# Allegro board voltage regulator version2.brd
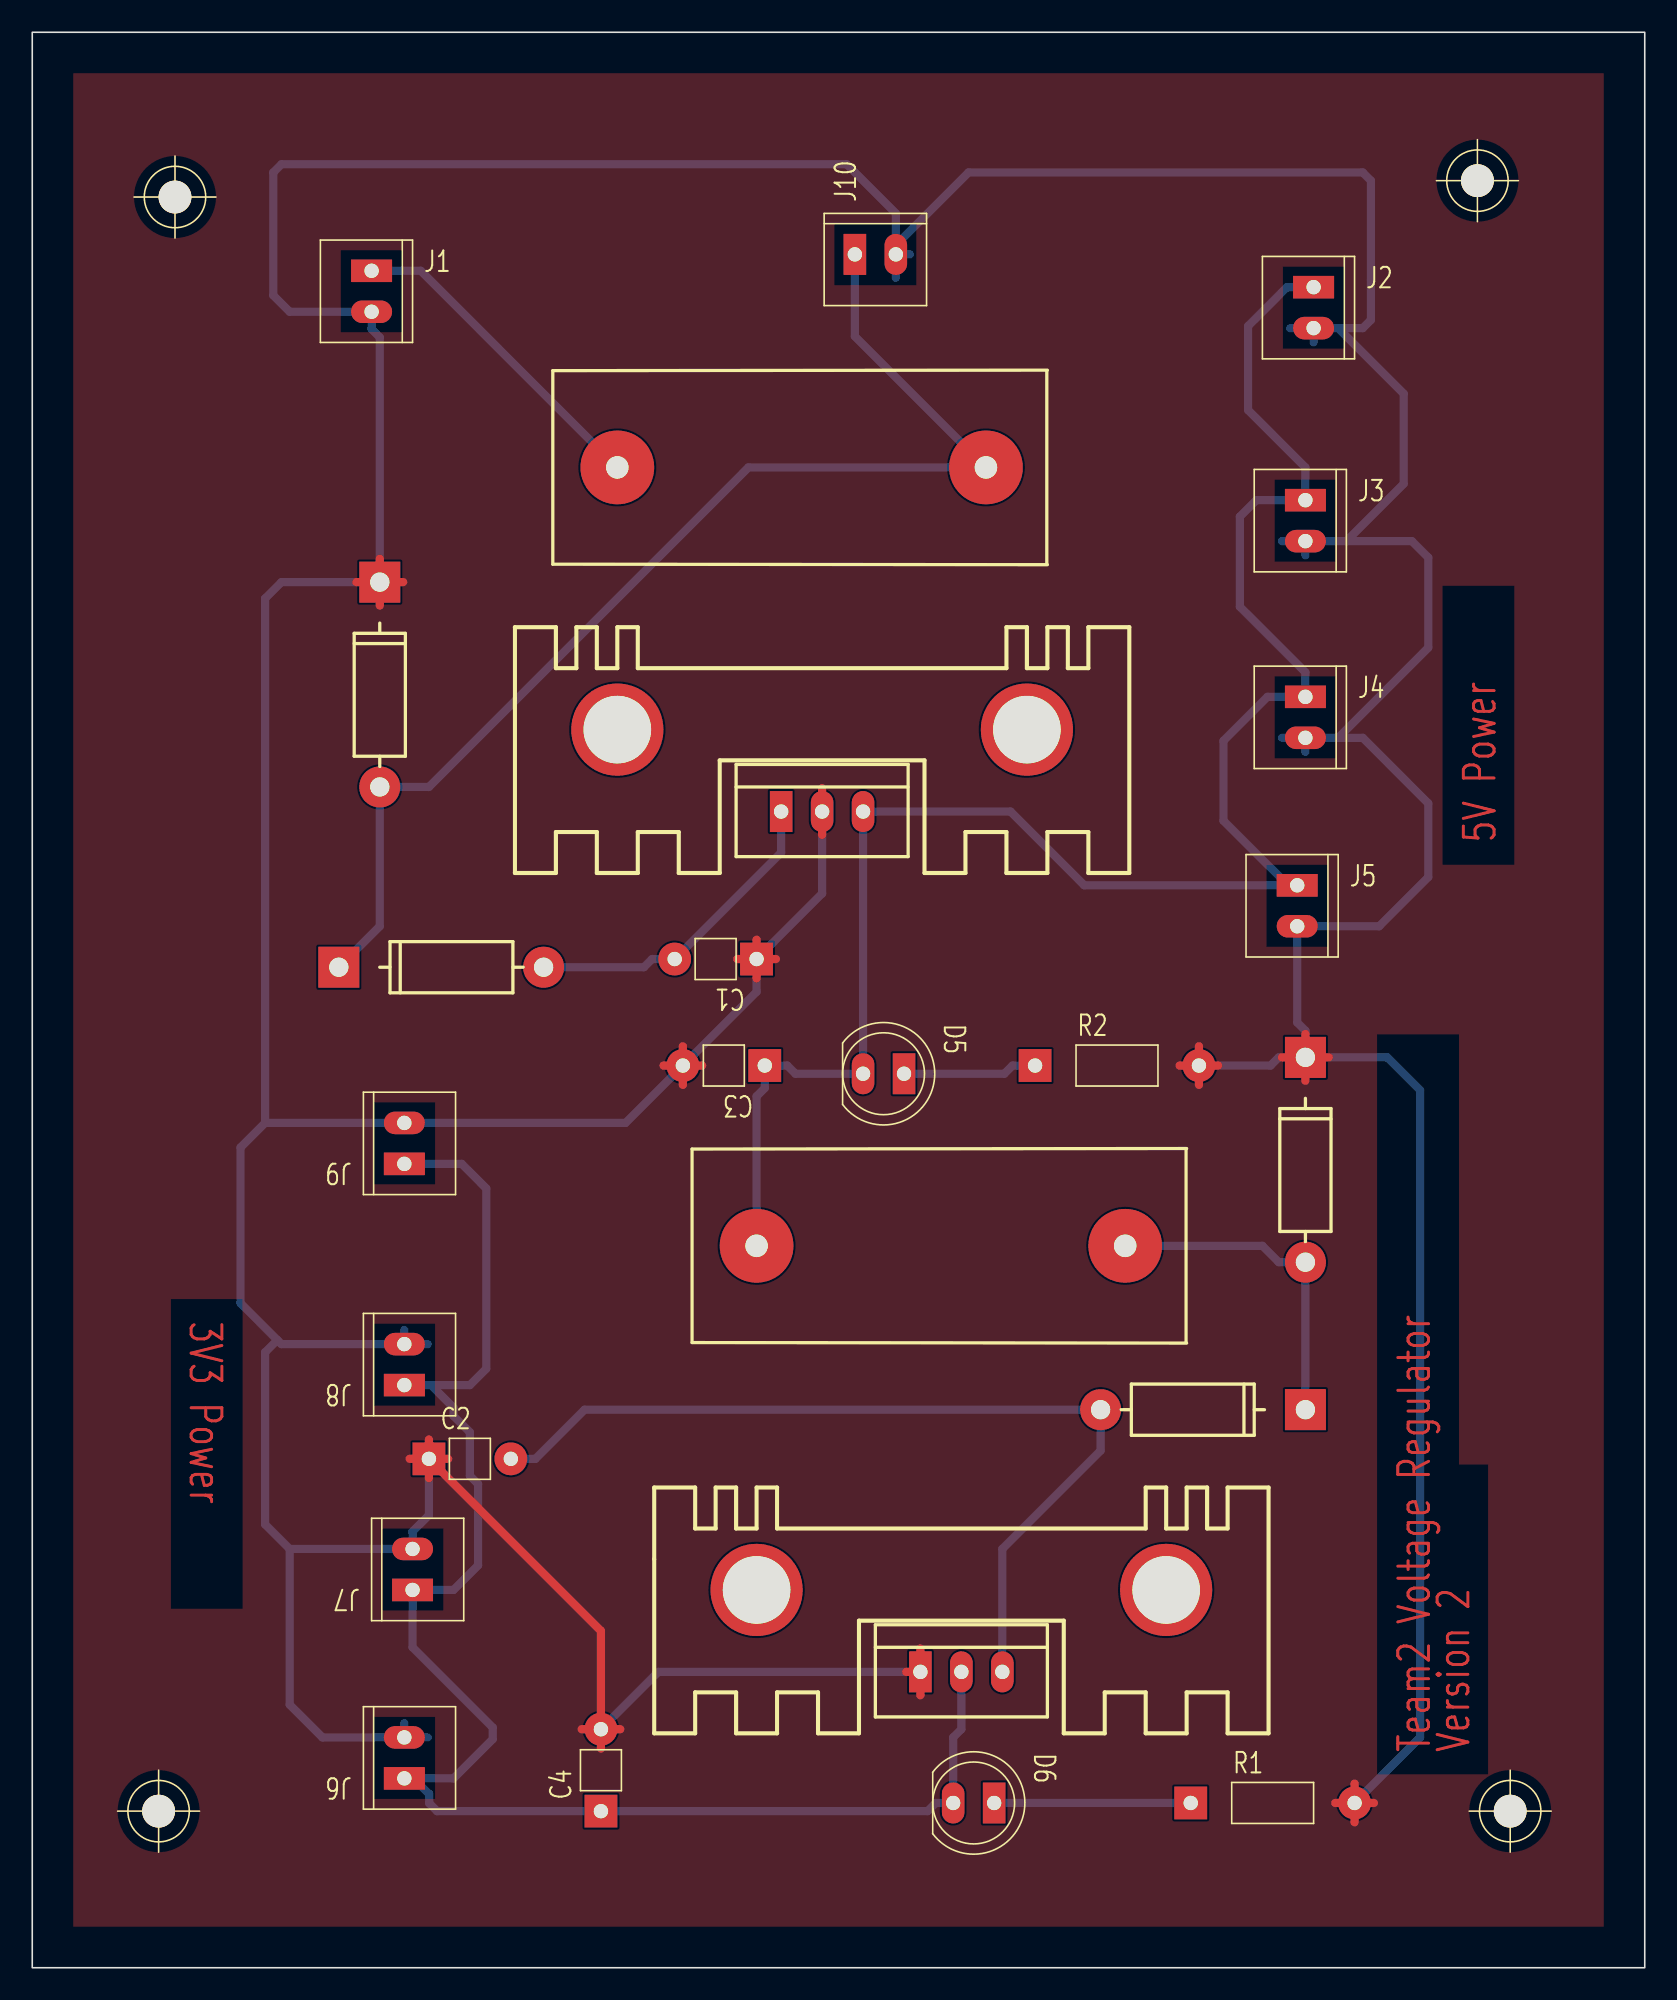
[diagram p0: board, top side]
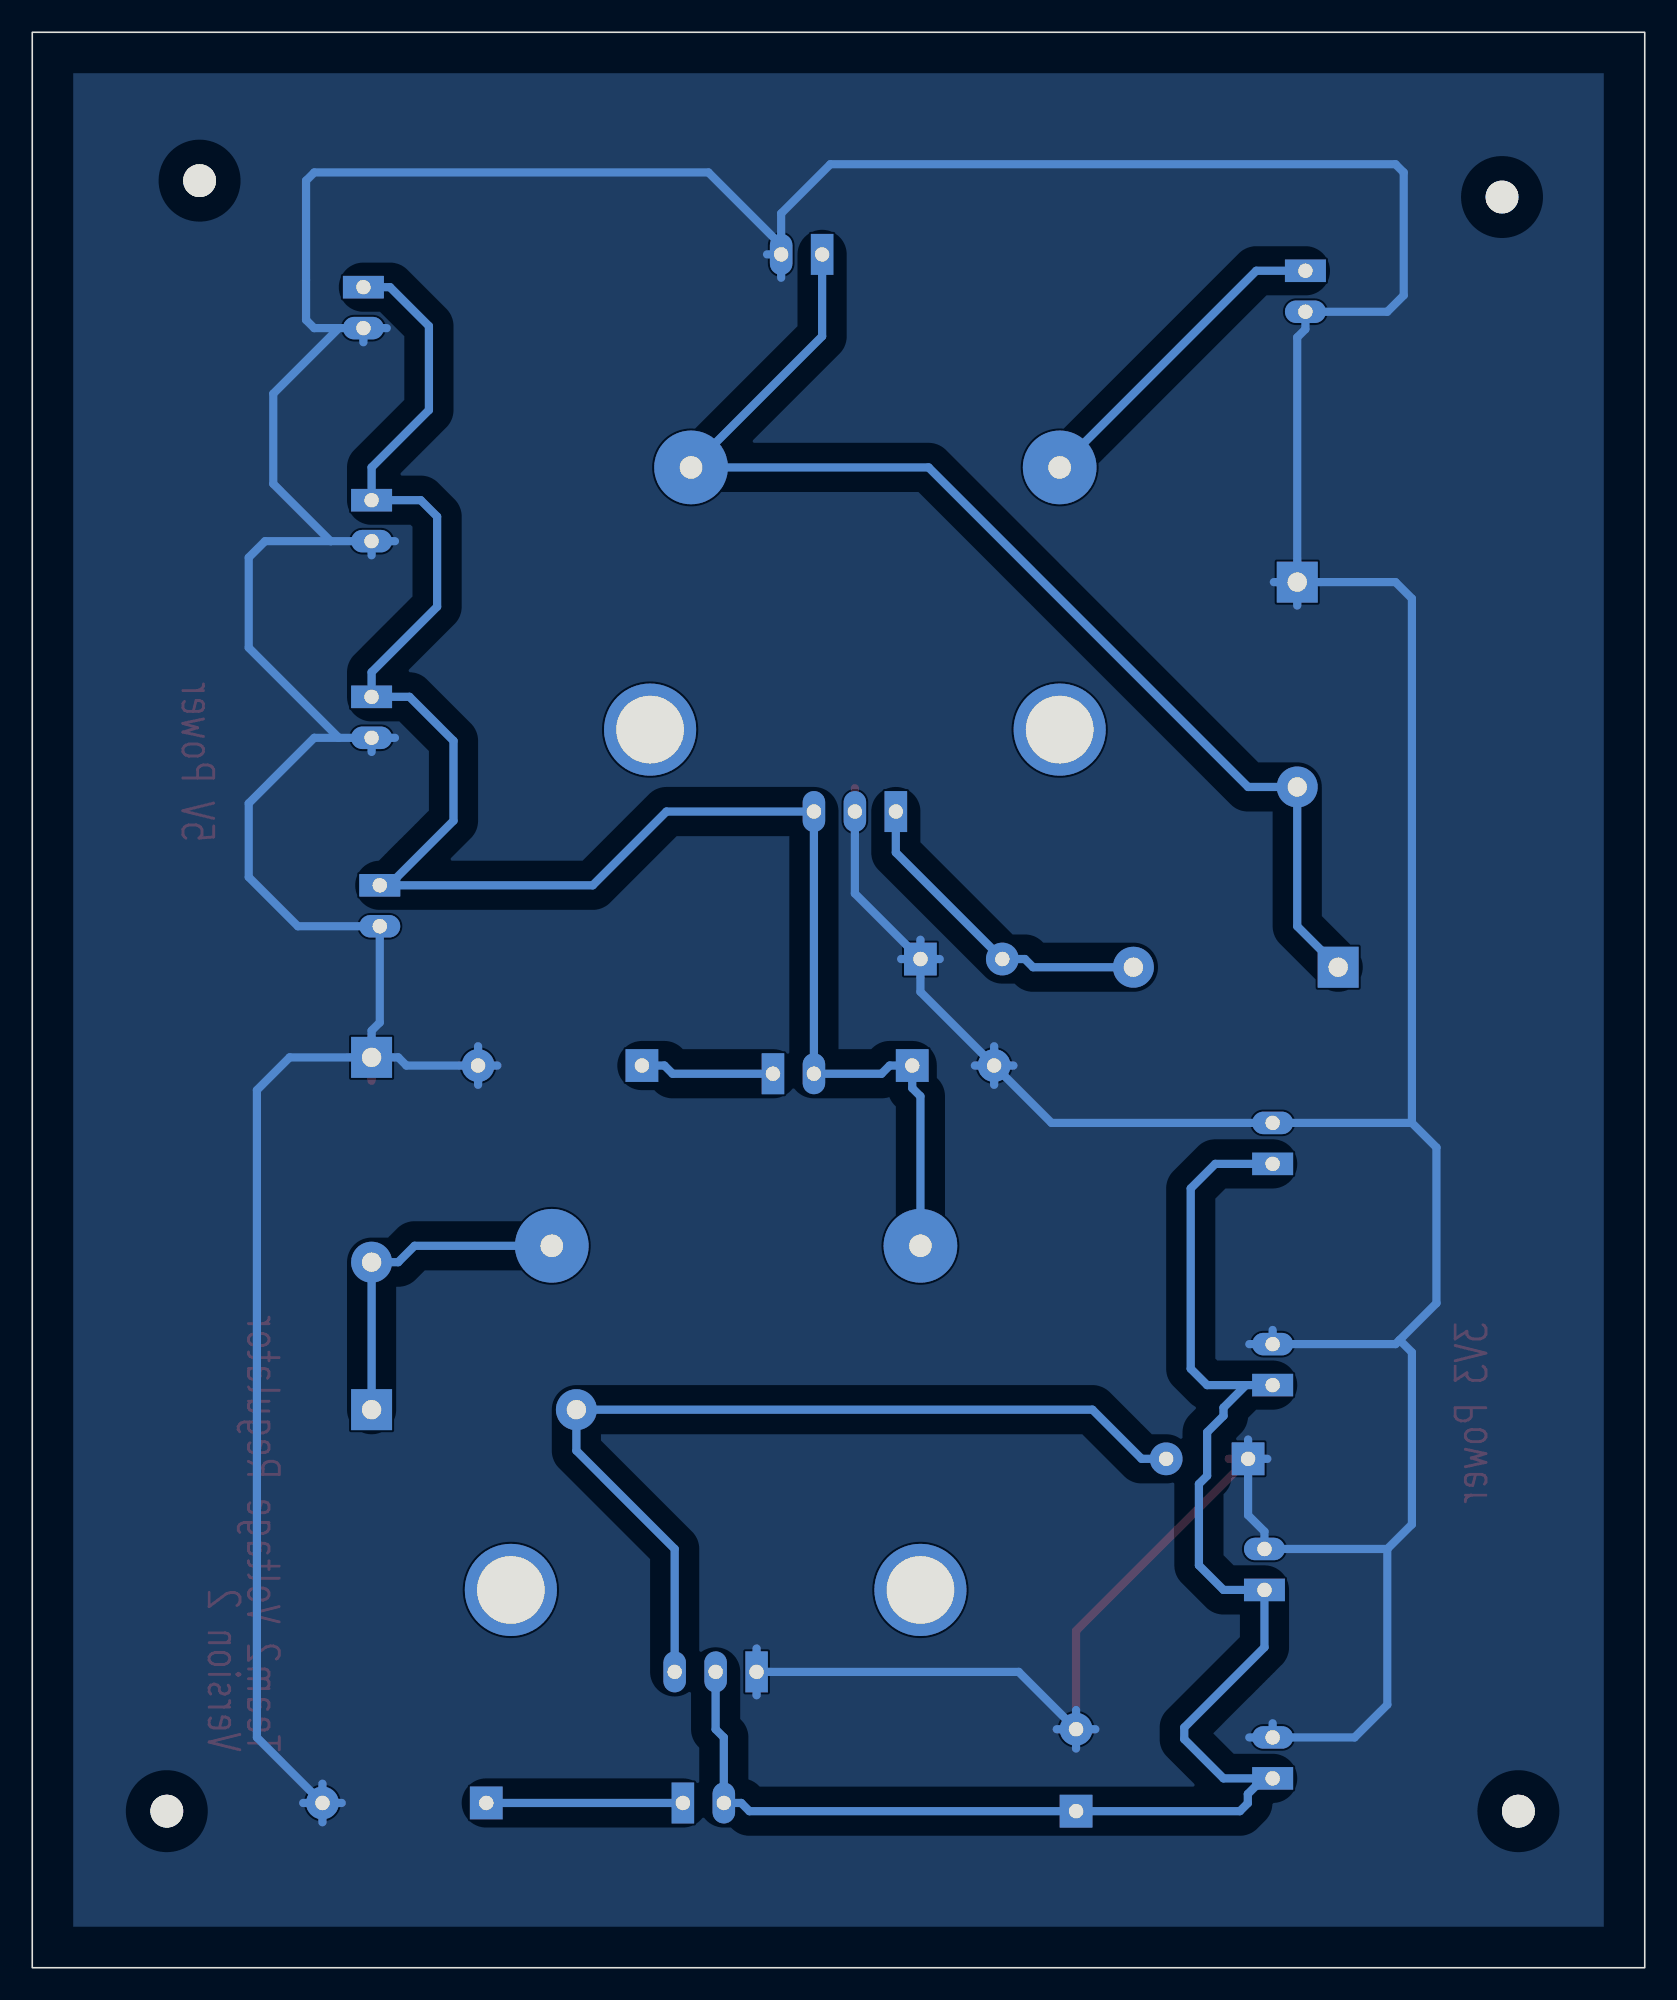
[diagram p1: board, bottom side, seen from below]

Outline 100 x 120 mm; copper layers: TOP, BOTTOM. Coordinates in mm from the lower left corner of the outline.
Outline path: rectangle 0,0 100,120

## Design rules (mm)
constraint set DEFAULT: min track width 0.508

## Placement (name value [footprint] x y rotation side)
C1  470n  [GU-RC200]  44.92 62.54 180 top
C2  100n  [GU-RC200]  24.6 31.55 0 top
C3  220n  [GU-RC200]  45.43 55.94 180 top
C4  10u  [GU-RC200]  35.27 9.71 90 top
D1  DIODE ZENER  [GU-1N4001]  78.96 56.44 270 top
D2  DIODE ZENER  [GU-1N4001]  21.55 85.91 270 top
D5  LED  [GU-LED5MM]  54.06 55.43 270 top
D6  LED  [GU-LED5MM]  59.65 10.22 270 top
D7  DIODE  [GU-1N4001]  19.01 62.03 0 top
D8  DIODE  [GU-1N4001]  78.96 34.6 180 top
F1  FUSEHOLDER  [GU-FUSEHOLDER-20MM]  36.28 93.02 0 top
F2  FUSEHOLDER  [GU-FUSEHOLDER-20MM]  44.92 44.76 0 top
J1  Battery Input  [GU-MOLEX2]  21.04 105.21 0 top
J2  5V Supply  [GU-MOLEX2]  79.46 104.2 0 top
J3  5V Supply  [GU-MOLEX2]  78.96 90.99 0 top
J4  5V Supply  [GU-MOLEX2]  78.96 78.8 0 top
J5  5V Supply  [GU-MOLEX2]  78.45 67.11 0 top
J6  3V3 Supply  [GU-MOLEX2]  23.08 11.74 180 top
J7  3V3 Supply  [GU-MOLEX2]  23.58 23.42 180 top
J8  3V3 Supply  [GU-MOLEX2]  23.08 36.12 180 top
J9  3V3 Supply  [GU-MOLEX2]  23.08 49.84 180 top
J10  12V Supply  [GU-MOLEX2]  51.02 106.23 90 top
NOREF  -  [unnamed]  8.85 109.78 0 top
NOREF#2  -  [unnamed]  91.66 9.71 0 top
NOREF#3  -  [unnamed]  89.62 110.8 0 top
NOREF#4  -  [unnamed]  7.84 9.71 0 top
R1  430  [GU-RC400]  71.84 10.22 0 top
R2  430  [GU-RC400]  62.19 55.94 0 top
U1  L7805/TO220  [GU-TO220AB-HSINK]  46.44 71.68 0 top
U2  LD1117/DD  [GU-TO220AB-HSINK]  55.08 18.34 0 top

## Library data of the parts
C1-C4 = CAP NP
D1 D2 = DIODE ZENER
D5 D6 = LED
D7 D8 = DIODE
F1 F2 = FUSEHOLDER
J1-J10 = CON2
R1 R2 = R
U1 = L7805/TO220_0
U2 = LD1117/DD_0

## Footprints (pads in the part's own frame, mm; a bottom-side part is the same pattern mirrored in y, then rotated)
GU-1N4001
  round 2.54 hole 1.194: 1(12.7,0)
  rect 2.54x2.54 hole 1.194: 2(0,0)
GU-FUSEHOLDER-20MM
  round 4.572 hole 1.397: 1(0,0) 2(22.86,0)
GU-LED5MM
  rect 2.54x1.397 hole 0.889: 1(0,0)
  oval 2.54x1.397 hole 0.889: 2(0,-2.54)
GU-MOLEX2
  rect 2.54x1.397 hole 0.889: 1(0,0)
  oval 2.54x1.397 hole 0.889: 2(0,-2.54)
GU-RC200
  rect 2.032x2.032 hole 0.889: 1(0,0)
  round 2.032 hole 0.889: 2(5.08,0)
GU-RC400
  rect 2.032x2.032 hole 0.889: 1(0,0)
  round 2.032 hole 0.889: 2(10.16,0)
GU-TO220AB-HSINK
  round 5.715 hole 4.191 unplated: (-10.16,5.08) (15.24,5.08)
  rect 1.397x2.54 hole 0.889: 1(0,0)
  oval 1.397x2.54 hole 0.889: 2(2.54,0) 3(5.08,0)
unnamed
  round 2.032 hole 3.962 unplated: (0,0)

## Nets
3.3V: C4.1 D6.2 J6.1 J7.1 J8.1 J9.1 U2.2(VOUT)
5V: C3.1 D5.2 F2.1 J2.1 J3.1 J4.1 J5.1 U1.3(VOUT)
12V: D2.1(CATHODE) D7.2 F1.2 J10.1
GND: C1.1 C2.1 C3.2 C4.2 D1.2 D2.2 J1.2 J2.2 J3.2 J4.2 J5.2 J6.2 J7.2 J8.2 J9.2 J10.2 R1.2 R2.2 U1.2 U2.1
N00466: D5.1(CATHODE) R2.1
N00539: F1.1 J1.1
N00628: D1.1(CATHODE) D8.2 F2.2
N00681: D6.1(CATHODE) R1.1
N03779: C1.2 D7.1(K) U1.1
N03792: C2.2 D8.1(K) U2.3

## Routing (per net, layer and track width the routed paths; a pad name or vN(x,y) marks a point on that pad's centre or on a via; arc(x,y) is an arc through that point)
3.3V: length 100.5
  BOTTOM w0.508: 23.65,11.74 24.62,10.77 24.62,10.2 25.11,9.71 C4.1 55.52,9.71 56.03,10.22 D6.2 57.11,14.28 57.62,14.79 U2.2 ; 23.65,11.74 J6.1 ; 23.65,11.74 26.12,11.74 28.56,14.17 28.56,14.89 23.58,19.87 J7.1 26.12,23.42 27.65,24.95 27.65,29.99 27.14,30.5 27.14,33.2 26.12,34.22 26.12,34.73 24.73,36.12 ; J9.1 26.63,49.84 28.16,48.32 28.16,37.14 27.14,36.12 24.73,36.12 ; 24.73,36.12 J8.1
5V: length 114.3
  BOTTOM w0.508: J5.1 77.88,67.11 ; 77.88,67.11 73.88,71.11 73.88,76.07 76.6,78.8 J4.1 78.96,80.32 74.89,84.38 74.89,89.97 75.91,90.99 J3.1 78.96,93.02 75.4,96.58 75.4,101.78 77.81,104.2 J2.1 ; 77.88,67.11 65.24,67.11 60.67,71.68 U1.3 D5.2 47.33,55.43 46.82,55.94 C3.1 45.43,54.54 44.92,54.03 F2.1
12V: length 74.6
  BOTTOM w0.508: J10.1 51.02,101.15 F1.2 44.41,93.02 24.6,73.21 D2.1 21.55,64.57 D7.2
GND: length 534.6
  TOP w0.508: 72.35,54.74 R2.2 ; R2.2 73.55,55.94 ; R2.2 71.16,55.94 ; R2.2 72.35,57.13 ; 80.81,10.22 R1.2 ; R1.2 82,9.02 ; R1.2 83.2,10.22 ; R1.2 82,11.41 ; 21.55,84.46 D2.2 ; D2.2 21.55,87.36 ; D2.2 23,85.91 ; D2.2 20.1,85.91 ; 34.07,14.79 C4.2 ; C4.2 36.46,14.79 ; C4.2 35.27,20.88 C2.1 ; C4.2 35.27,13.59 ; 55.08,16.9 U2.1 ; U2.1 54.2,18.34 ; U2.1 55.08,19.79 ; C2.1 24.6,32.75 ; C2.1 25.79,31.55 ; C2.1 23.41,31.55 ; C2.1 24.6,30.36 ; 44.92,61.35 C1.1 ; C1.1 43.73,62.54 ; C1.1 44.92,63.73 ; C1.1 46.11,62.54 ; 40.35,54.74 C3.2 ; C3.2 39.15,55.94 ; C3.2 41.54,55.94 ; C3.2 40.35,57.13 ; 48.98,73.13 U1.2 48.98,70.24 ; D1.2 80.4,56.44 ; D1.2 78.96,57.89 ; D1.2 77.51,56.44 ; D1.2 78.96,55
  BOTTOM w0.508: 15.96,25.96 15.96,16.31 18,14.28 J6.2 ; 15.96,25.96 14.44,27.49 14.44,38.16 15.2,38.92 ; 15.96,25.96 J7.2 23.58,27.04 24.6,28.06 C2.1 ; C1.1 46.11,62.54 ; C1.1 48.98,66.6 U1.2 ; C1.1 44.92,63.73 ; C1.1 43.73,62.54 ; C1.1 44.92,60.51 C3.2 ; J8.2 23.08,39.54 ; J8.2 15.46,38.66 15.2,38.92 ; J8.2 24.52,38.66 ; 81.5,88.45 85.56,88.45 86.58,87.43 86.58,81.84 80.99,76.26 ; 81.5,88.45 J3.2 ; 81.5,88.45 85.05,92 85.05,97.59 80.99,101.66 ; 82,9.02 R1.2 ; R1.2 80.81,10.22 ; R1.2 82,11.41 ; R1.2 86.07,14.28 86.07,54.41 84.04,56.44 D1.2 ; R1.2 83.2,10.22 ; C3.2 40.35,57.13 ; C3.2 36.79,52.38 J9.2 14.44,52.38 ; C3.2 40.35,54.74 ; C3.2 39.15,55.94 ; C3.2 41.54,55.94 ; 14.44,52.38 14.44,84.89 15.46,85.91 D2.2 ; 14.44,52.38 12.92,50.86 12.92,41.2 15.2,38.92 ; C4.2 38.82,18.34 U2.1 ; C4.2 35.27,13.59 ; C4.2 36.46,14.79 ; C4.2 35.27,15.98 ; C4.2 34.07,14.79 ; 79.46,100.78 J2.2 ; J2.2 78.02,101.66 ; J2.2 80.99,101.66 ; 80.99,76.26 82.51,76.26 86.58,72.19 86.58,67.62 83.53,64.57 J5.2 78.45,58.6 78.96,58.09 D1.2 ; 80.99,76.26 J4.2 ; 77.51,88.45 J3.2 ; J3.2 78.96,87.57 ; J10.2 54.43,106.23 ; J10.2 53.56,106.8 ; J10.2 53.56,104.78 ; C2.1 23.41,31.55 ; C2.1 24.6,32.75 ; J6.2 23.08,15.16 ; J6.2 24.52,14.28 ; R2.2 76.8,55.94 77.3,56.44 D1.2 ; R2.2 72.35,57.13 ; R2.2 72.35,54.74 ; R2.2 71.16,55.94 ; 53.56,106.8 53.56,108.77 50.51,111.82 15.46,111.82 14.95,111.31 14.95,103.69 15.96,102.67 J1.2 21.04,101.59 21.55,101.08 D2.2 ; 53.56,106.8 58.06,111.31 82.51,111.31 83.02,110.8 83.02,102.16 82.51,101.66 80.99,101.66 ; 21.55,84.46 D2.2 ; D2.2 23,85.91 ; 77.51,76.26 J4.2 ; J4.2 78.96,75.38 ; U2.1 55.08,19.79 ; U2.1 55.08,16.9
N00466: length 8.3
  BOTTOM w0.508: D5.1 60.29,55.43 60.79,55.94 R2.1
N00539: length 20.3
  BOTTOM w0.508: F1.1 24.09,105.21 J1.1
N00628: length 20.7
  BOTTOM w0.508: D8.2 D1.1 77.3,43.74 76.29,44.76 F2.2
N00681: length 12.2
  BOTTOM w0.508: D6.1 R1.1
N03779: length 20.2
  BOTTOM w0.508: U1.1 46.44,69.14 C1.2 38.44,62.54 37.93,62.03 D7.1
N03792: length 56.6
  BOTTOM w0.508: C2.2 31.2,31.55 34.25,34.6 D8.1 66.26,32.06 60.16,25.96 U2.3

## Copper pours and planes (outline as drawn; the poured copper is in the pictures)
GND on TOP, BOTTOM: 2.54,117.46 97.46,117.46 97.46,2.54 2.54,2.54

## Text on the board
TOP: Team2 Voltage Regulator | Version 2 | 5V Power | 3V3 Power
